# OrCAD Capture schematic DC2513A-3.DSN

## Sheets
1 PAGE2: size A
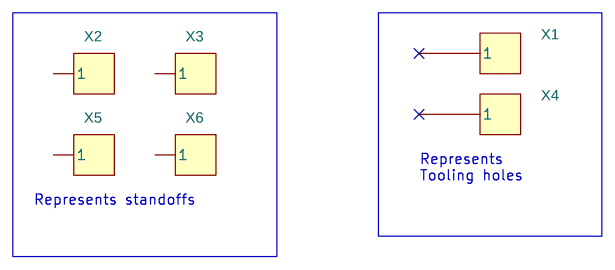
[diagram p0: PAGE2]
2 PAGE1: size Custom; title: HIGH DENSITY HYBRID STEP-DOWN; rev: 3; note: DEMO CIRCUIT 2513A
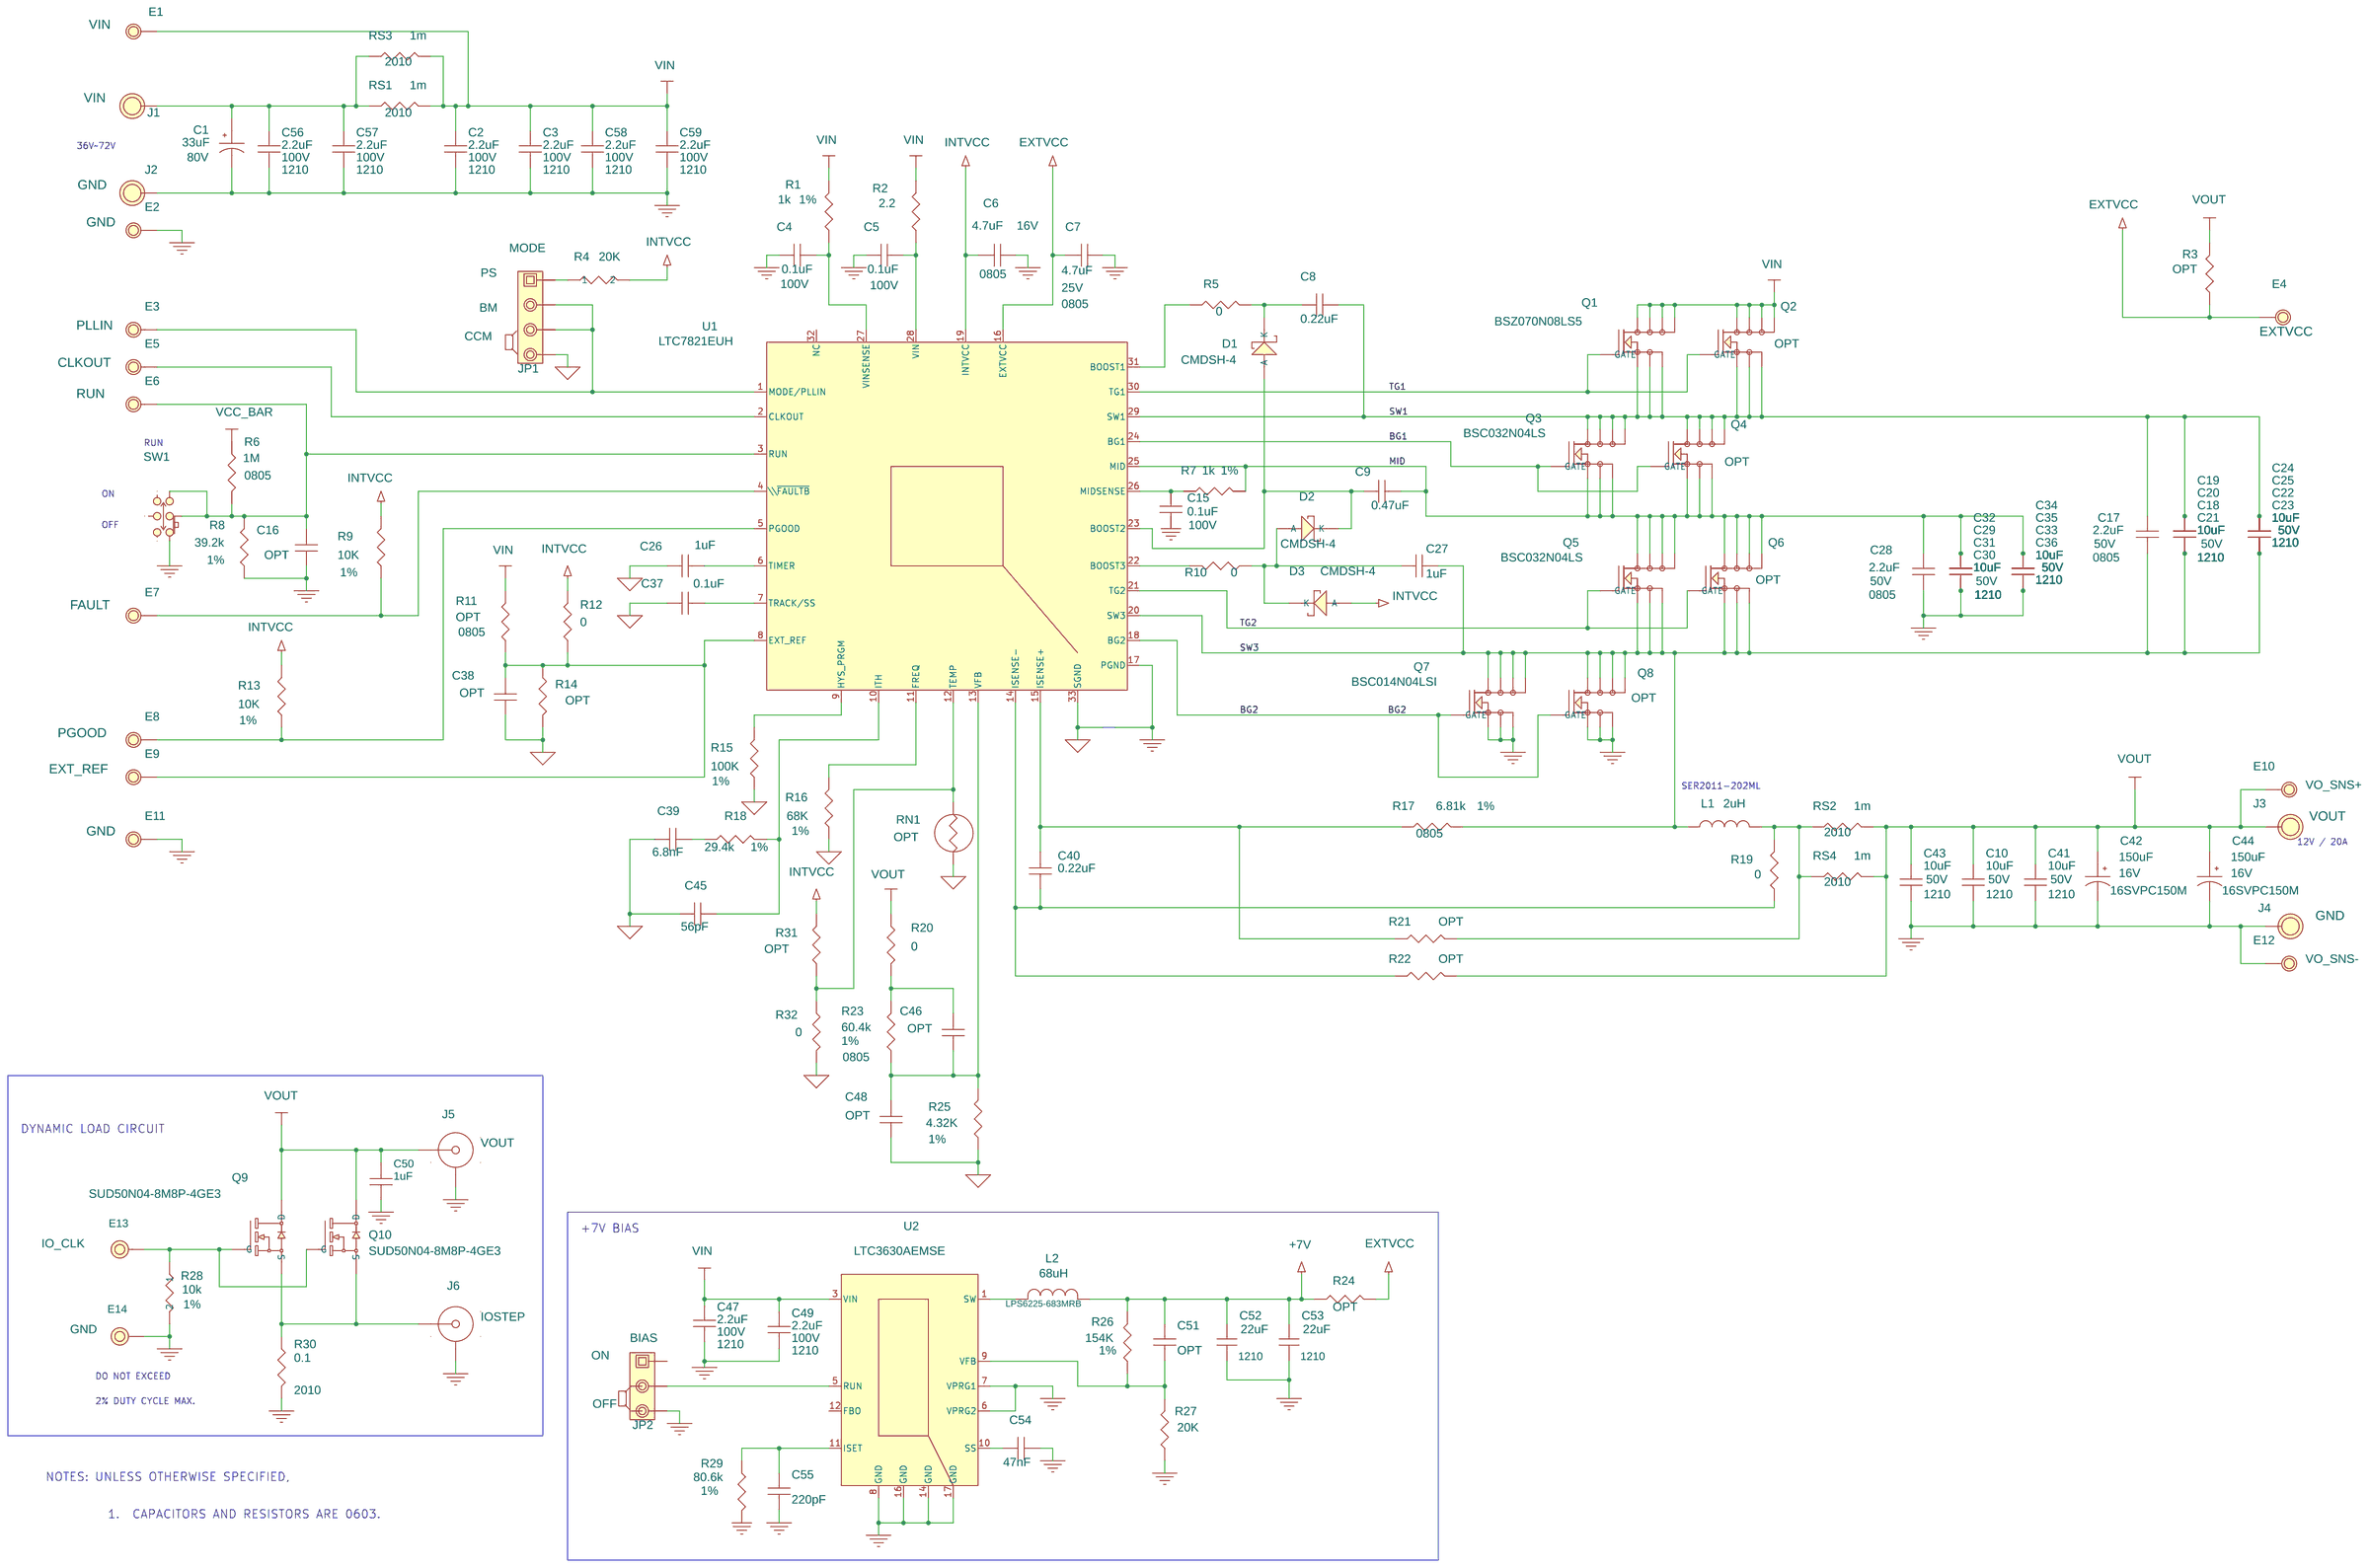
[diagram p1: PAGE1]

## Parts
sheet PAGE1
C1  33uF  [CAP\SANYO\10X10.2\CE]
C2  2.2uF  [1210]
C3  2.2uF  [1210]
C4  0.1uF  [0603]
C5  0.1uF  [0603]
C6  4.7uF  [0805]
C7  4.7uF  [0805]
C8  0.22uF  [0603]
C9  0.47uF  [0603]
C10  10uF  [1210]
C15  0.1uF  [0603]
C16  OPT  [0603]
C17  2.2uF  [0805]
C18  10uF  [1210]
C19  10uF  [1210]
C20  10uF  [1210]
C21  10uF  [1210]
C22  10uF  [1210]
C23  10uF  [1210]
C24  10uF  [1210]
C25  10uF  [1210]
C26  1uF  [0603]
C27  1uF  [0603]
C28  2.2uF  [0805]
C29  10uF  [1210]
C30  10uF  [1210]
C31  10uF  [1210]
C32  10uF  [1210]
C33  10uF  [1210]
C34  10uF  [1210]
C35  10uF  [1210]
C36  10uF  [1210]
C37  0.1uF  [0603]
C38  OPT  [0603]
C39  6.8nF  [0603]
C40  0.22uF  [0603]
C41  10uF  [1210]
C42  150uF  [CAP\SANYO\SVPA_E7]
C43  10uF  [1210]
C44  150uF  [CAP\SANYO\SVPA_E7]
C45  56pF  [0603]
C46  OPT  [0603]
C47  2.2uF  [1210]
C48  OPT  [0603]
C49  2.2uF  [1210]
C50  1uF  [0603]
C51  OPT  [0603]
C52  22uF  [1210]
C53  22uF  [1210]
C54  47nF  [0603]
C55  220pF  [0603]
C56  2.2uF  [1210]
C57  2.2uF  [1210]
C58  2.2uF  [1210]
C59  2.2uF  [1210]
D1  CMDSH-4  [SOD323]
D2  CMDSH-4  [SOD323]
D3  CMDSH-4  [SOD323]
E1  VIN  [MILLMAX-2501-2]
E2  GND  [MILLMAX-2501-2]
E3  PLLIN  [MILLMAX-2501-2]
E4  EXTVCC  [MILLMAX-2501-2]
E5  CLKOUT  [MILLMAX-2501-2]
E6  RUN  [MILLMAX-2501-2]
E7  FAULT  [MILLMAX-2501-2]
E8  PGOOD  [MILLMAX-2501-2]
E9  EXT_REF  [MILLMAX-2501-2]
E10  VO_SNS+  [MILLMAX-2501-2]
E11  GND  [MILLMAX-2501-2]
E12  VO_SNS-  [MILLMAX-2501-2]
E13  Testpoint  [MILLMAX-2501-2]
E14  Testpoint  [MILLMAX-2501-2]
J1  VIN  [RP325/205]
J2  GND  [RP325/205]
J3  VOUT  [RP325/205]
J4  GND  [RP325/205]
J5  Connector  [BNC5]
J6  Connector  [BNC5]
JP1  3 Pins 2mm Ctrs.  [HDR_1X4_2MM]
JP2  3 Pins 2mm Ctrs.  [HD1X3-079]
L1  2uH  [IND\CLCRFT\SER2010-102ML]
L2  68uH  [IND\CLCRFT\LPS6225]
Q1  BSZ070N08LS5  [PWRPK_SO8]
Q2  OPT  [PWRPK_SO8]
Q3  BSC032N04LS  [PWRPK_SO8]
Q4  OPT  [PWRPK_SO8]
Q5  BSC032N04LS  [PWRPK_SO8]
Q6  OPT  [PWRPK_SO8]
Q7  BSC014N04LSI  [PWRPK_SO8]
Q8  OPT  [PWRPK_SO8]
Q9  30V  [TO252-3]
Q10  30V  [TO252-3]
R1  1k  [0603]
R2  2.2  [0603]
R3  OPT  [0603]
R4  20K  [0603]
R5  0  [0603]
R6  1M  [0805]
R7  1k  [0603]
R8  39.2k  [0603]
R9  10K  [0603]
R10  0  [0603]
R11  OPT  [0805]
R12  0  [0603]
R13  10K  [0603]
R14  OPT  [0603]
R15  100K  [0603]
R16  68K  [0603]
R17  6.81k  [0805]
R18  29.4k  [0603]
R19  0  [0603]
R20  0  [0603]
R21  OPT  [0603]
R22  OPT  [0603]
R23  60.4k  [0805]
R24  OPT  [0603]
R25  4.32K  [0603]
R26  154K  [0603]
R27  20K  [0603]
R28  10k  [0603]
R29  80.6k  [0603]
R30  0.1  [2010]
R31  OPT  [0603]
R32  0  [0603]
RN1  OPT  [0603]
RS1  1m  [2010]
RS2  1m  [2010]
RS3  1m  [2010]
RS4  1m  [2010]
SW1  JP3X1/079\NO\12  [JS202011]
U1  LTC7821EUH  [LT_UH32_5X5]
U2  LTC3630AEMSE  [LT_MSE16_12]
XJP1  2mm Ctrs.
XJP2  2mm Ctrs.
sheet PAGE2
X1  CON1  [PAD70-70]
X2  CON1  [KEYSTONE_8831]
X3  CON1  [KEYSTONE_8831]
X4  CON1  [PAD70-70]
X5  CON1  [KEYSTONE_8831]
X6  CON1  [KEYSTONE_8831]

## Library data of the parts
C1 = CAP_POL: CAP, 33uF 20% 80V POLYMER HYBRID ALUM ELEC; Part Number: PANASONIC EEHZA1K330P; VOLTAGE: 80V
C2 C3 C47 C49 C56-C59 = CAP_NP: CAP, 1210 2.2uF 10% 100V X7R; COMPFIXED: 100V; Part Number: MURATA GRM32DR72A225KA12K
C4 C5 C15 C37 = CAP_NP_0: CAP, 0603 0.1uF 10% 100V X7R; Part Number: MURATA GRM188R72A104KA35D; VOLTAGE: 100V
C6 = CAP_NP_3: CAP, 0805 4.7uF 10% 16V X7R; Part Number: MURATA GRM21BR71C475KA73K; Voltage: 16V
C7 = CAP_NP_3: CAP, 0805 4.7uF 10% 25V X7R; Part Number: MURATA GRM21BR71E475KA73L; Voltage: 25V
C8 = EMK107BJ224MA: CAP, 0603 0.22uF 10% 25V X7R; 6th Part Field: (Opt); Part Number: MURATA GRM188R71E224KA88D
C9 = EMK107BJ224MA: CAP, 0603 0.47uF 10% 25V X7R; 6th Part Field: (Opt); Part Number: MURATA GRM188R71E474KA12D
C10 C22-C25 C33-C36 C41 C43 = CAP_NP: CAP, 1210 10uF 10% 50V X7R; Part Number: MURATA GRM32ER71H106KA12L; Voltage: 50V
C16 C38 C46 C48 = CAP_NP_0: CAP, 0603 OPTION; Part Number: OPTION
C17 C28 = CAP_NP: CAP, 0805 2.2uF 10% 50V X7R; Part Number: TDK C2012X7R1H225K125AC; VOLTAGE: 50V
C18-C21 C29-C32 = CAP_NP: CAP, 1210 10uF 10% 50V X7R; Part Number: MURATA GRM32ER71H106KA12L; VOLTAGE: 50V
C26 = CAP_NP_0: CAP, 0603 1uF 20% 25V X5R; Part Number: AVX 06033D105MAT2A
C27 = EMK107BJ224MA: CAP, 0603 1uF 20% 25V X5R; 6th Part Field: (Opt); Part Number: AVX 06033D105MAT2A
C39 = CAP: CAP.,6800pF,X7R,50V,10%,0603; CLASS: DISCRETE; Dielectric Type: X7R; FPLIST: CC0603N,CC0603L,CC0603M; Manufacturer: AVX; Manufacturer PN: 06035C682KAT2A; PART_NUMBER: 150-3409; Part Number: AVX 06035C682KAT2A; Rated Voltage: 50V; Tolerance: 10%
C40 = CAP_NP: CAP, 0603 0.22uF 10% 25V X7R; Part Number: MURATA GRM188R71E224KA88D; Tolerance: X7R
C42 C44 = CAP_POL: CAP, 150uF 20% 16V; MANUFACTURING: 16SVPC150M; Part Number: PANASONIC 16SVPC150M; VOLTAGE: 16V
C45 = CAP: CAP.,56pF,C0G,50V,5%,0603; CLASS: DISCRETE; Dielectric Type: C0G; FPLIST: CC0603N,CC0603L,CC0603M; Manufacturer: MURATA; Manufacturer PN: GRM1885C1H560JA01D; PART_NUMBER: 150-0104; Part Number: MURATA GRM1885C1H560JA01D; Rated Voltage: 50V; Tolerance: 5%
C50 = TMK107BJ105MA: CAP, 0603 1uF 20% 25V X5R; Part Number: AVX 06033D105MAT2A
C51 = CAP_NP: CAP, 0603 OPTION; Part Number: OPTION
C52 = GRM32ER61226KE15: CAP, 1210 22uF 10% 25V X5R; Part Number: AVX 12103D226KAT2A
C53 = GRM32ER61226KE15_1: CAP, 1210 22uF 10% 25V X5R; Part Number: AVX 12103D226KAT2A
C54 = CAP_NP: CAP, 0603 47nF 10% 25V X7R; Part Number: AVX 06033C473KAT2A
C55 = CAP_NP: CAP, 0603 220pF 10% 50V X7R; Part Number: AVX 06035C221KAT2A
D1-D3 = cmdsh-3_1: DIODE, SCHOTTKY; Component: diode; Manufacturer: Central; Manufacturer P/N: CMDSH-3TR; Part Number: CENTRAL SEMI. CMDSH-4E.TR LEAD-FREE; Type: Schottky; Vendor: Mouser; Vendor P/N: 610-CMDSH-3; Volts/Amps/Watts: 30V 100mA
E1-E12 = E_1: TURRET; Part Number: MILL-MAX 2501-2-00-80-00-00-07-0; STATUS: 1.6V, 1.8V, 2.0V OR 2.5V @ 15A
E13 = MillMax-2501-2: TURRET; 9th Part Field: IO_CLK; Part Number: MILL-MAX 2501-2-00-80-00-00-07-0
E14 = MillMax-2501-2: TURRET; 9th Part Field: GND; Part Number: MILL-MAX 2501-2-00-80-00-00-07-0
J1-J4 = E_4: JACK, BANANA; Part Number: KEYSTONE 575-4; STATUS: 1.6V, 1.8V, 2.0V OR 2.5V @ 15A
J5 = Connex_112404_gnd2_0: CON, BNC, 5 PINS; 10th Part Field: 5% DUTY CYCLE MAX.; 11th Part Field: 10mV / A; 7th Part Field: BNC; 9th Part Field: VOUT; Part Number: CONNEX 112404
J6 = Connex_112404_gnd2_0_1: CON, BNC, 5 PINS; 10th Part Field: 5% DUTY CYCLE MAX.; 11th Part Field: 10mV / A; 7th Part Field: BNC; 9th Part Field: IOSTEP; Part Number: CONNEX 112404
JP1 = Samtec_TMM-103-02-L-S_0: HEADER, 4PIN, 2mm; 11th Part Field: PS; 12th Part Field: MODE; 4th Part Field: CCM; 5th Part Field: SYNC; 9th Part Field: BM; Part Number: WURTH ELEKTRONIK 6200041121
JP2 = Samtec_TMM-103-02-L-S: HEADER, 3PIN 2mm; 11th Part Field: OFF; 12th Part Field: BIAS; 9th Part Field: ON; Part Number: WURTH ELEKTRONIK 6200031121
L1 = INDUCTOR: IND, 2uH 20%; Part Number: COILCRAFT SER2011-202MLD; manufacturing: Coilcraft SER1360-472KL
L2 = IND-TDK-VLF: IND, 68uH; 5TH PART FIELD: LPS6225-683MRB; Part Number: COILCRAFT LPS6225-683MRB
Q1 = SI4410: XSTR, N-CHANNEL MOSFET; Part Number: INFINEON BSZ070N08LS5ATMA1
Q2 Q4 Q6 Q8 = SI4410: XSTR, N-CHANNEL MOSFET OPTION; Part Number: OPTION
Q3 Q5 = SI4410: XSTR, N-CHANNEL MOSFET; Part Number: INFINEON BSC032N04LS
Q7 = SI4410: XSTR, N-CHANNEL MOSFET; Part Number: INFINEON BSC014N04LSI
Q9 Q10 = Si7806BDN_5: XSTR, MOSFET N-CHANNEL 40V TO-252; 5th Part Field: SUD50N04-8M8P-4GE3; Part Number: VISHAY SILICONIX SUD50N04-8M8P-4GE3
R1 = R_1: RES, 0603 1k OHMS 1% 0.1W; %: 1%; Part Number: VISHAY CRCW06031K00FKEA
R2 = R_1: RES, 0603 2.2 OHMS 5% 0.1W; %: 0.1%; Part Number: VISHAY CRCW06032R20JNEA
R3 R11 R14 R31 = R_1: RES, 0603 OPTION; %: 0.1%; Part Number: OPTION
R4 = R: RES, 0603 20K OHMS 1% 0.1W; Part Number: VISHAY CRCW060320K0FKEA
R5 R10 = CJ06-000M: RES, 0603 0 OHM JUMPER; 6th Part Field: (Opt); Part Number: VISHAY CRCW06030000Z0EA
R6 = R_1: RES, 0805 1M OHMS 1% 0.125W; %: 0.1%; Part Number: VISHAY CRCW08051M00FKEA
R7 = CJ06-000M: RES, 0603 1k OHMS 1% 0.1W; %: 1%; 6th Part Field: (Opt); Part Number: VISHAY CRCW06031K00FKEA
R8 = R_1: RES, 0603 39.2K OHMS 1% 1/10W; %: 1%; Part Number: VISHAY CRCW060339K2FKEA
R9 R13 = R_1: RES, 0603 10k OHMS 1% 0.1W; %: 1%; Part Number: VISHAY CRCW060310K0FKEA
R12 R19 R20 R32 = R_1: RES, 0603 0 OHM JUMPER; Part Number: VISHAY CRCW06030000Z0EA
R15 = R_1: RES, 0603 100k OHMS 1% 0.1W; %: 1%; Part Number: VISHAY CRCW0603100KFKEA
R16 = R_1: RES, 0603 68k OHMS 1% 0.1W; %: 1%; Part Number: VISHAY CRCW060368K0FKEA
R17 = CJ06-000M: RES, 0805 6.81k OHMS 1% 0.1W; 1st Part Field: 1%; 6th Part Field: (Opt); Part Number: VISHAY CRCW08056K81FKEA
R18 = R_1: RES, 0603 29.4k OHMS 1% 1/10W; %: 1%; Part Number: VISHAY CRCW060329K4FKEA
R21 R22 = CJ06-000M: RES, 0603 OPTION; 6th Part Field: (Opt); Part Number: OPTION
R23 = R_1: RES, 0805 60.4k OHM 1% 0.125W; %: 1%; Part Number: VISHAY CRCW080560K4FKEA
R24 = RESISTOR_1: RES, 0603 OPTION; Part Number: OPTION
R25 = R_1: RES, 0603 4.32k OHMS 1% 0.1W; %: 1%; Part Number: VISHAY CRCW06034K32FKEA
R26 = RESISTOR_1: RES, 0603 154K OHM 1% 0.1W; Part Number: VISHAY CRCW0603154KFKEA; Tolerance: 1%
R27 = RES0603_0: RES, 0603 20K OHMS 5% 0.1W; Manufacturer: Panasonic; Manufacturer P/N: ERJ-3EKF2002V; Part Number: VISHAY CRCW060320K0JNEA; Vendor: Digikey; Vendor P/N: P20.0KHCT-ND; Volts/Amps/Watts: 0.1W
R28 = CR16-103JM: RES, 0603 10k OHMS 1% 0.1W; %: 1%; Part Number: VISHAY CRCW060310K0FKEA
R29 = AAC-0603: RES, 0603 80.6k OHMS 1% 0.1W; 1ST PART FIELD: 1%; Part Number: VISHAY CRCW060380K6FKEA
R30 = LR2010-01-R020-F: RES. 2010 0.1 OHMS 1% 1W; Part Number: VISHAY WSL2010R1000FEA18
RN1 = RNTC: THERMISTOR, OPTION; Part Number: OPTION
RS1-RS4 = RES: RES.,2010 0.001 OHM 1% 2W; CLASS: DISCRETE; FPLIST: CR2010N,CR2010L,CR2010M; Manufacturer: PANASONIC; Manufacturer PN: ERJ-MP3PF1M0U; PART_NUMBER: P; Part Number: PANASONIC ERJ-MP3PF1M0U; Rated Power: 2W
SW1 = JP3X1_079_NO_12_3: SWITCH, SUBMINATURE SLIDE; Part Number: C&K JS202011CQN
U1 = LTC7821EUH_0: IC,; Part Number: LINEAR TECH. LTC7821EUH
U2 = LTC3630EMSE_0: IC, SYNCHRONOUS STEP-DOWN CONVERTER; Part Number: LINEAR TECH. LTC3630EMSE
XJP1 XJP2 = Samtec_2SN-BK-G: SHUNT 2mm; Part Number: WURTH ELEKTRONIK 60800213421
X1 X4 = CON1: PAD ONLY; Part Number: Not Used
X2 X3 X5 X6 = CON1_v2: STANDOFF, SNAP ON; Part Number: KEYSTONE 8834

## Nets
+7V: C51.1 C52.1 C53.1 L2.2 R24.1 R26.2
GND: C1.2 C2.2 C3.2 C4.1 C5.1 C6.2 C7.2 C10.2 C15.2 C16.1 C28.2 C29.2 C30.2 C31.2 C32.2 C33.2 C34.2 C35.2 C36.2 C41.2 C42.2 C43.2 C44.2 C47.2 C49.2 C50.1 C52.2 C53.2 C54.2 C55.2 C56.2 C57.2 C58.2 C59.2 E2.1(A) E11.1(A) E12.1(A) E14.1 J2.1(A) J4.1(A) J5.2(GND2) J5.3(GND) J5.4(GND) J5.5(GND) J6.2(GND2) J6.3(GND) J6.4(GND) J6.5(GND) JP2.3 Q7.1 Q7.2 Q7.3 Q8.1 Q8.2 Q8.3 R8.2 R27.1 R28.2 R29.2 R30.2 SW1.3 U1.17(PGND) U2.6(VPRG2) U2.7(VPRG1) U2.8(GND) U2.14(GND) U2.16(GND) U2.17(GND)
GND_SIGNAL: C26.1 C37.1 C38.1 C39.1 C45.1 C48.1 JP1.4 R14.2 R15.2 R16.2 R25.2 R32.1 RN1.1 U1.33(SGND)
VIN: C2.1 C3.1 C47.1 C49.1 C58.1 C59.1 E1.1(A) Q1.5 Q1.6 Q1.7 Q1.8 Q2.5 Q2.6 Q2.7 Q2.8 R1.1 R2.1 R6.1 R11.1 RS1.2 RS3.2 U2.3(VIN)
BG1: Q3.4(GATE) Q4.4(GATE) U1.24(BG1)
BG2: Q7.4(GATE) Q8.4(GATE) U1.18(BG2)
EXTVCC: C7.1 E4.1(A) R3.2 R24.2 U1.16(EXTVCC)
INTVCC: C6.1 D3.2(A) R4.2 R9.1 R12.2 R13.1 R31.1 U1.19(INTVCC)
MID: C9.2 C28.1 C29.1 C30.1 C31.1 C32.1 C33.1 C34.1 C35.1 C36.1 Q3.1 Q3.2 Q3.3 Q4.1 Q4.2 Q4.3 Q5.5 Q5.6 Q5.7 Q5.8 Q6.5 Q6.6 Q6.7 Q6.8 R7.2 U1.25(MID)
SW1: C8.2 C17.1 C18.1 C19.1 C20.1 C21.1 C22.1 C23.1 C24.1 C25.1 Q1.1 Q1.2 Q1.3 Q2.1 Q2.2 Q2.3 Q3.5 Q3.6 Q3.7 Q3.8 Q4.5 Q4.6 Q4.7 Q4.8 U1.29(SW1)
SW3: C17.2 C18.2 C19.2 C20.2 C21.2 C22.2 C23.2 C24.2 C25.2 C27.2 L1.2 Q5.1 Q5.2 Q5.3 Q6.1 Q6.2 Q6.3 Q7.5 Q7.6 Q7.7 Q7.8 Q8.5 Q8.6 Q8.7 Q8.8 R17.2 U1.20(SW3)
TG1: Q1.4(GATE) Q2.4(GATE) U1.30(TG1)
TG2: Q5.4(GATE) Q6.4(GATE) U1.21(TG2)
VOUT: C10.1 C41.1 C42.1 C43.1 C44.1 C50.2 E10.1(A) J3.1(A) J5.1 Q9.2(D) Q10.2(D) R3.1 R20.2 R22.2 RS2.2 RS4.2
N04584: C38.2 E9.1(A) R11.2 R12.1 R14.1 U1.8(EXT_REF)
N04686: R15.1 U1.9(HYS_PRGM)
N04784: C46.1 C48.2 R23.2 R25.1 U1.13(VFB)
N04800: R16.1 U1.11(FREQ)
N04822: C45.2 R18.1 U1.10(ITH)
N04982: R31.2 R32.2 RN1.2 U1.12(TEMP)
N05002: C5.2 R2.2 U1.28(VIN)
N05038: C27.1 D2.2(A) D3.1(K) R10.2
N05084: E13.1 Q9.1(G) Q10.1(G) R28.1
N05104: J6.1 Q9.3(S) Q10.3(S) R30.1
N05368: JP2.2 U2.5(RUN)
N05504: L1.1 R19.1 R21.2 RS2.1 RS4.1
N05534: C4.2 R1.2 U1.27(VINSENSE)
N05586: C40.1 R19.2 R22.1 U1.14(ISENSE-)
N05654: R10.1 U1.22(BOOST3)
N05658: C55.1 R29.1 U2.11(ISET)
N05746: C40.2 R17.1 R21.1 U1.15(ISENSE+)
N05854: C1.1 C56.1 C57.1 J1.1(A) RS1.1 RS3.1
N06460: R5.1 U1.31(BOOST1)
N06468: C8.1 D1.1(K) R5.2
N06596: C54.1 U2.10(SS)
N06760: C9.1 D1.2(A) D2.1(K) U1.23(BOOST2)
N06780: C51.2 R26.1 R27.2 U2.9(VFB)
N06948: C15.1 R7.1 U1.26(MIDSENSE)
N06986: C16.2 E6.1(A) R6.2 R8.1 SW1.1 SW1.2 U1.3(RUN)
N07284: C46.2 R20.1 R23.1
N07504: C39.2 R18.2
N07606: E3.1(A) JP1.2 JP1.3 U1.1(MODE/PLLIN)
N07846: L2.1 U2.1(SW)
N08326: E7.1(A) R9.2 U1.4(\\~{FAULTB})
N08330: E8.1(A) R13.2 U1.5(PGOOD)
N08430: E5.1(A) U1.2(CLKOUT)
N08786: JP1.1 R4.1
N08826: C26.2 U1.6(TIMER)
N09082: C37.2 U1.7(TRACK/SS)

Not connected (* = marked no-connect by the designer): JP2 1; SW1 4 5 6; U1 32(NC); U2 12(FBO); X1 1*; X2 1; X3 1; X4 1*; X5 1; X6 1

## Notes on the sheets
sheet 1
- Represents
  Tooling holes
- Represents standoffs
sheet 2
- 36V~72V
- RUN
- ON
- OFF
- SER2011-202ML
- 12V / 20A
- DYNAMIC LOAD CIRCUIT
- +7V BIAS
- DO NOT EXCEED
- 2% DUTY CYCLE MAX.
- NOTES: UNLESS OTHERWISE SPECIFIED,
- 1.  CAPACITORS AND RESISTORS ARE 0603.
